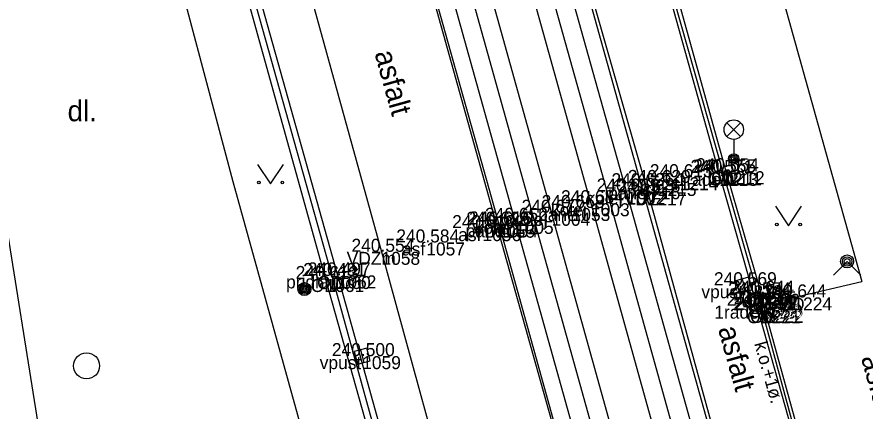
# Model space of a CAD drawing. Extents: x -599098 to -598820, y -1159597 to -1158744.
# Drawn here: x -598980.81 to -598948.19, y -1159125.79 to -1159110.65 of the extents above; entities that cross this region are included whole.
import ezdxf

# ---------------------------------------------------------------- set-up
doc = ezdxf.new("R2010")
doc.units = 0
for name, color, linetype in [('body', 7, 'Continuous'), ('dešťové vpusti šachty', 7, 'Continuous'), ('druh pozemku stromy', 7, 'Continuous'), ('kresba', 7, 'Continuous'), ('kódy bodů', 7, 'Continuous'), ('popisy', 7, 'Continuous'), ('tram_koleje', 7, 'Continuous'), ('tram_osa', 7, 'Continuous'), ('vodorovné dopravní značení_bílé', 7, 'Continuous'), ('vodorovné dopravní značení_modré', 7, 'Continuous'), ('výšky bodů', 7, 'Continuous'), ('značky IS', 7, 'Continuous'), ('čísla bodů', 7, 'Continuous')]:
    doc.layers.add(name, color=color, linetype=linetype)

msp = doc.modelspace()

# ---------------------------------------------------------------- linework, layer by layer
at = {"layer": 'body'}
for p, q in [((-598953.795, -1159116.637), (-598953.795, -1159116.637)), ((-598953.648, -1159116.62), (-598953.648, -1159116.62)), ((-598953.539, -1159116.575), (-598953.539, -1159116.575)), ((-598955.316, -1159116.804), (-598955.316, -1159116.804)), ((-598956.783, -1159117.151), (-598956.783, -1159117.151)), ((-598956.159, -1159117.025), (-598956.159, -1159117.025)), ((-598957.359, -1159117.355), (-598957.359, -1159117.355)), ((-598956.549, -1159117.387), (-598956.549, -1159117.387)), ((-598959.476, -1159117.986), (-598959.476, -1159117.986)), ((-598958.731, -1159117.805), (-598958.731, -1159117.805)), ((-598960.248, -1159118.171), (-598960.248, -1159118.171)), ((-598962.368, -1159118.629), (-598962.368, -1159118.629)), ((-598962.261, -1159118.617), (-598962.261, -1159118.617)), ((-598961.655, -1159118.481), (-598961.655, -1159118.481)), ((-598962.903, -1159118.761), (-598962.903, -1159118.761)), ((-598965.065, -1159119.311), (-598965.065, -1159119.311)), ((-598966.789, -1159119.67), (-598966.789, -1159119.67)), ((-598968.689, -1159120.6), (-598968.689, -1159120.6)), ((-598968.472, -1159120.576), (-598968.472, -1159120.576)), ((-598968.937, -1159120.715), (-598968.937, -1159120.715)), ((-598952.85, -1159120.955), (-598952.85, -1159120.955)), ((-598952.307, -1159121.341), (-598952.307, -1159121.341)), ((-598952.181, -1159121.282), (-598952.181, -1159121.282)), ((-598950.946, -1159121.423), (-598950.946, -1159121.423)), ((-598952.347, -1159121.739), (-598952.347, -1159121.739)), ((-598952.09, -1159121.691), (-598952.09, -1159121.691)), ((-598952.042, -1159121.901), (-598952.042, -1159121.901)), ((-598952.157, -1159121.914), (-598952.157, -1159121.914)), ((-598967.529, -1159123.678), (-598967.529, -1159123.678))]:
    msp.add_line(p, q, dxfattribs=at)
at = {"layer": 'dešťové vpusti šachty'}
for p, q in [((-598952.919, -1159120.715), (-598952.781, -1159121.195)), ((-598967.589, -1159123.435), (-598967.469, -1159123.921))]:
    msp.add_line(p, q, dxfattribs=at)
for points in [[(-598953.159, -1159120.783), (-598953.022, -1159121.264), (-598952.541, -1159121.127), (-598952.678, -1159120.646)], [(-598967.832, -1159123.496), (-598967.711, -1159123.981), (-598967.226, -1159123.86), (-598967.347, -1159123.375)]]:
    msp.add_lwpolyline(points, close=True, dxfattribs=at)
at = {"layer": 'druh pozemku stromy'}
for points in [[(-598971.55, -1159116.31), (-598971.05, -1159117.06), (-598970.55, -1159116.31)], [(-598951.635, -1159117.919), (-598951.135, -1159118.669), (-598950.635, -1159117.919)]]:
    msp.add_lwpolyline(points, dxfattribs=at)
for centre in [(-598971.5, -1159117.01), (-598970.601, -1159117.01), (-598951.585, -1159118.619), (-598950.686, -1159118.619)]:
    msp.add_circle(centre, 0.05, dxfattribs=at)
at = {"layer": 'kresba'}
for p, q in [((-598968.633, -1159048.261), (-598948.308, -1159120.805)), ((-598953.795, -1159116.637), (-598956.883, -1159105.637)), ((-598953.648, -1159116.62), (-598956.755, -1159105.672)), ((-598956.606, -1159105.607), (-598953.539, -1159116.575)), ((-598959.827, -1159106.287), (-598956.783, -1159117.151)), ((-598962.261, -1159118.617), (-598965.278, -1159107.892)), ((-598971.989, -1159109.75), (-598968.937, -1159120.715)), ((-598968.689, -1159120.6), (-598971.752, -1159109.679)), ((-598968.472, -1159120.576), (-598971.549, -1159109.603)), ((-598952.347, -1159121.739), (-598953.795, -1159116.637)), ((-598952.307, -1159121.341), (-598953.648, -1159116.62)), ((-598953.539, -1159116.575), (-598952.181, -1159121.282)), ((-598956.783, -1159117.151), (-598953.712, -1159128.146)), ((-598959.185, -1159129.67), (-598962.261, -1159118.617)), ((-598965.578, -1159131.808), (-598968.689, -1159120.6)), ((-598965.333, -1159131.795), (-598968.472, -1159120.576)), ((-598968.937, -1159120.715), (-598965.8, -1159131.899)), ((-598950.946, -1159121.423), (-598948.308, -1159120.805)), ((-598952.307, -1159121.341), (-598952.157, -1159121.914)), ((-598952.09, -1159121.691), (-598952.181, -1159121.282)), ((-598952.09, -1159121.691), (-598950.946, -1159121.423)), ((-598950.775, -1159127.328), (-598952.347, -1159121.739)), ((-598952.042, -1159121.901), (-598952.09, -1159121.691)), ((-598950.577, -1159127.242), (-598952.042, -1159121.901)), ((-598952.157, -1159121.914), (-598950.699, -1159127.295))]:
    msp.add_line(p, q, dxfattribs=at)
for points in [[(-598977.18, -1159099.38), (-598972.5, -1159116.97), (-598969.43, -1159128.06), (-598968.43, -1159127.79), (-598968.15, -1159129.52), (-598968.01, -1159129.52), (-598967.61, -1159132.09), (-598967.33, -1159132.06), (-598964.25, -1159143.25), (-598963.95, -1159144.36)], [(-598979.12, -1159131.74), (-598981.14, -1159119.03), (-598982.53, -1159119.26)]]:
    msp.add_lwpolyline(points, dxfattribs=at)
at = {"layer": 'tram_koleje'}
for p, q in [((-598957.359, -1159117.355), (-598960.42, -1159106.451)), ((-598958.731, -1159117.805), (-598961.803, -1159106.841)), ((-598963.304, -1159107.224), (-598960.248, -1159118.171)), ((-598964.703, -1159107.559), (-598961.655, -1159118.481)), ((-598954.284, -1159128.404), (-598957.359, -1159117.355)), ((-598958.731, -1159117.805), (-598955.669, -1159128.798)), ((-598957.198, -1159129.11), (-598960.248, -1159118.171)), ((-598961.655, -1159118.481), (-598958.588, -1159129.488))]:
    msp.add_line(p, q, dxfattribs=at)
at = {"layer": 'tram_osa'}
for points in [[(-598938.102, -1159189.074), (-598940.508, -1159180.437), (-598943.529, -1159169.556), (-598946.566, -1159158.78), (-598949.609, -1159147.796), (-598952.764, -1159136.53), (-598954.976, -1159128.601), (-598958.045, -1159117.58), (-598961.111, -1159106.646), (-598964.189, -1159095.51), (-598967.312, -1159084.422), (-598970.303, -1159073.667), (-598973.399, -1159062.532), (-598976.544, -1159051.232), (-598977.385, -1159048.26), (-598978.019, -1159046.002), (-598979.646, -1159040.156)], [(-598982.522, -1159040.899), (-598980.786, -1159047.126), (-598980.207, -1159049.207), (-598979.432, -1159052.01), (-598976.294, -1159063.274), (-598973.186, -1159074.433), (-598970.188, -1159085.191), (-598967.115, -1159096.22), (-598964.003, -1159107.391), (-598960.951, -1159118.326), (-598957.893, -1159129.299), (-598955.658, -1159137.315), (-598952.52, -1159148.606), (-598949.451, -1159159.509), (-598946.474, -1159170.204), (-598943.386, -1159181.246), (-598941.005, -1159189.804)]]:
    msp.add_lwpolyline(points, dxfattribs=at)
at = {"layer": 'vodorovné dopravní značení_bílé'}
for points in [[(-599004.61, -1158945.262), (-599003.444, -1158949.453), (-598994.165, -1158982.574), (-598991.03, -1158993.767), (-598984.936, -1159015.967), (-598978.352, -1159039.475), (-598975.241, -1159050.571), (-598972.159, -1159061.595), (-598965.954, -1159083.858), (-598959.703, -1159106.35), (-598956.549, -1159117.387), (-598953.462, -1159128.573), (-598948.06, -1159147.837), (-598944.998, -1159159.054), (-598943.117, -1159165.778)], [(-598973.022, -1159080.32), (-598971.525, -1159085.618), (-598968.451, -1159096.839), (-598962.368, -1159118.629), (-598959.252, -1159129.728), (-598957.149, -1159137.573), (-598954.079, -1159148.322)]]:
    msp.add_lwpolyline(points, dxfattribs=at)
at = {"layer": 'vodorovné dopravní značení_modré'}
msp.add_lwpolyline([(-598974.717, -1159097.673), (-598973.301, -1159096.019), (-598972.813, -1159097.76), (-598969.71, -1159109.09), (-598966.789, -1159119.67), (-598963.616, -1159131.223), (-598961.587, -1159138.462), (-598960.736, -1159141.45), (-598962.866, -1159140.558)], dxfattribs=at)
at = {"layer": 'značky IS'}
for p, q in [((-598953.505, -1159115.24), (-598952.975, -1159114.71)), ((-598953.505, -1159114.71), (-598952.975, -1159115.24)), ((-598953.24, -1159115.35), (-598953.24, -1159116.1))]:
    msp.add_line(p, q, dxfattribs=at)
msp.add_lwpolyline([(-598949.41, -1159120.57), (-598948.88, -1159120.04), (-598948.35, -1159120.57)], dxfattribs=at)
for centre, radius in [((-598953.24, -1159114.975), 0.375), ((-598953.24, -1159116.1), 0.2), ((-598953.24, -1159116.1), 0.145), ((-598953.24, -1159116.1), 0.0876), ((-598948.88, -1159120.04), 0.25), ((-598948.88, -1159120.04), 0.18), ((-598948.88, -1159120.04), 0.11), ((-598969.75, -1159121.1), 0.25), ((-598969.75, -1159121.1), 0.2), ((-598969.75, -1159121.1), 0.15), ((-598969.75, -1159121.1), 0.1), ((-598969.75, -1159121.1), 0.05), ((-598978.13, -1159124.05), 0.5)]:
    msp.add_circle(centre, radius, dxfattribs=at)

# ---------------------------------------------------------------- texts
at = {"layer": 'kódy bodů'}
for s, p in [('1rade', (-598955.435, -1159117.137)), ('OD', (-598954.22, -1159117.12)), ('ON', (-598954.109, -1159117.075)), ('asf', (-598957.092, -1159117.525)), ('asf', (-598956.249, -1159117.304)), ('kolej', (-598958.899, -1159117.855)), ('pane', (-598958.073, -1159117.651)), ('VDZ', (-598957.469, -1159117.887)), ('kolej', (-598960.271, -1159118.305)), ('kolej', (-598961.788, -1159118.671)), ('pane', (-598960.766, -1159118.486)), ('VDZ', (-598963.288, -1159119.129)), ('kolej', (-598963.195, -1159118.981)), ('asf', (-598963.836, -1159119.261)), ('pane', (-598963.551, -1159119.117)), ('asf', (-598965.998, -1159119.811)), ('VDZm', (-598968.128, -1159120.17)), ('pridla', (-598970.458, -1159121.076)), ('OD', (-598969.261, -1159121.1)), ('ON', (-598969.507, -1159121.215)), ('vpust', (-598954.485, -1159121.455)), ('OD', (-598952.879, -1159121.841)), ('ON', (-598952.751, -1159121.782)), ('OD', (-598951.518, -1159121.923)), ('1rade', (-598953.987, -1159122.239)), ('OD', (-598952.729, -1159122.414)), ('ON', (-598952.66, -1159122.191)), ('ON', (-598952.612, -1159122.401)), ('vpust', (-598969.164, -1159124.178))]:
    msp.add_text(s, height=0.5, dxfattribs=at).set_placement(p)
at = {"layer": 'popisy'}
for s, height, rotation, p in [('asfalt', 0.8, 285.5601, (-598967.061, -1159112.038)), ('asfalt', 0.8, 285.5601, (-598953.849, -1159122.627)), ('k.o.+1ø.', 0.5, 285.7095, (-598952.456, -1159123.197)), ('asfalt', 0.8, 285.5601, (-598948.351, -1159123.742))]:
    msp.add_text(s, height=height, rotation=rotation, dxfattribs=at).set_placement(p)
msp.add_text('dl.', height=0.8, dxfattribs=at).set_placement((-598978.861, -1159114.655))
at = {"layer": 'výšky bodů'}
for s, p in [('240.613', (-598956.468, -1159116.804)), ('240.571', (-598954.903, -1159116.637)), ('240.555', (-598954.8, -1159116.62)), ('240.654', (-598954.691, -1159116.575)), ('240.636', (-598957.943, -1159117.151)), ('240.629', (-598957.311, -1159117.025)), ('240.669', (-598958.511, -1159117.355)), ('240.626', (-598957.709, -1159117.387)), ('240.684', (-598959.883, -1159117.805)), ('240.677', (-598961.4, -1159118.171)), ('240.668', (-598960.628, -1159117.986)), ('240.652', (-598962.807, -1159118.481)), ('240.610', (-598964.069, -1159118.761)), ('240.628', (-598963.52, -1159118.629)), ('240.616', (-598963.421, -1159118.617)), ('240.584', (-598966.217, -1159119.311)), ('240.554', (-598967.941, -1159119.67)), ('240.613', (-598970.089, -1159120.715)), ('240.491', (-598969.797, -1159120.6)), ('240.497', (-598969.624, -1159120.576)), ('240.569', (-598954.002, -1159120.955)), ('240.554', (-598953.459, -1159121.341)), ('240.644', (-598953.333, -1159121.282)), ('240.644', (-598952.098, -1159121.423)), ('240.556', (-598953.507, -1159121.739)), ('240.605', (-598953.242, -1159121.691)), ('240.551', (-598953.265, -1159121.914)), ('240.592', (-598953.194, -1159121.901)), ('240.500', (-598968.695, -1159123.678))]:
    msp.add_text(s, height=0.5, dxfattribs=at).set_placement(p)
at = {"layer": 'čísla bodů'}
for s, p in [('1213', (-598953.795, -1159117.137)), ('1211', (-598953.648, -1159117.12)), ('1212', (-598953.539, -1159117.075)), ('1215', (-598956.159, -1159117.525)), ('1214', (-598955.316, -1159117.304)), ('1216', (-598956.783, -1159117.651)), ('1002', (-598957.359, -1159117.855)), ('1217', (-598956.549, -1159117.887)), ('1053', (-598959.476, -1159118.486)), ('1003', (-598958.731, -1159118.305)), ('1004', (-598960.248, -1159118.671)), ('1055', (-598962.368, -1159119.129)), ('1054', (-598962.261, -1159119.117)), ('1005', (-598961.655, -1159118.981)), ('1056', (-598962.903, -1159119.261)), ('1057', (-598965.065, -1159119.811)), ('1058', (-598966.789, -1159120.17)), ('1060', (-598968.689, -1159121.1)), ('1062', (-598968.472, -1159121.076)), ('1061', (-598968.937, -1159121.215)), ('1218', (-598952.85, -1159121.455)), ('1219', (-598952.307, -1159121.841)), ('1220', (-598952.181, -1159121.782)), ('1224', (-598950.946, -1159121.923)), ('1225', (-598952.347, -1159122.239)), ('1221', (-598952.157, -1159122.414)), ('1223', (-598952.09, -1159122.191)), ('1222', (-598952.042, -1159122.401)), ('1059', (-598967.529, -1159124.178))]:
    msp.add_text(s, height=0.5, dxfattribs=at).set_placement(p)

doc.saveas('drawing.dxf')
